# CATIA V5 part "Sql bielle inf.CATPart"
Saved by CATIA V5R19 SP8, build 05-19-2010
Part number: Sql bielle inf
Publications: "Droite.1", "Plan.1", "Droite.2", "Droite.3"
Bounding box of the stored display mesh (mm): x 100 to 400, y -20 to 20, z -200 to -200
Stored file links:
  C:\Users\ThinkMotion\Desktop\EU_thinkMotion\iao\IAO_MMS_Groupe3\rdalborgo\rdalborgo\Sql bielle inf.CATPart
  C:\Users\ThinkMotion\Desktop\EU_thinkMotion\iao\IAO_MMS_Groupe3\rdalborgo\rdalborgo\Sql train.CATProduct
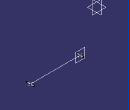
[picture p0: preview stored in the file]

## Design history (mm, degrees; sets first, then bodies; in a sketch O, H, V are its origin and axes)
Set1
  Point1 "D bielle": linked copy from another document
  Point2 "C bielle": linked copy from another document
  Plane1: linked copy from another document
Set2
  Line1: type PtPt, FirstPoint Point1, SecondPoint Point2
  Plane2: type OffsetPt, RefPlane Plane1, RefPoint Point1
  Line2: type Normal, RefPoint Point1, RefSkin Plane1, Start -20, End 20
  Line3: type Normal, RefPoint Point2, RefSkin Plane1, Start -20, End 20
Body1 (main body)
